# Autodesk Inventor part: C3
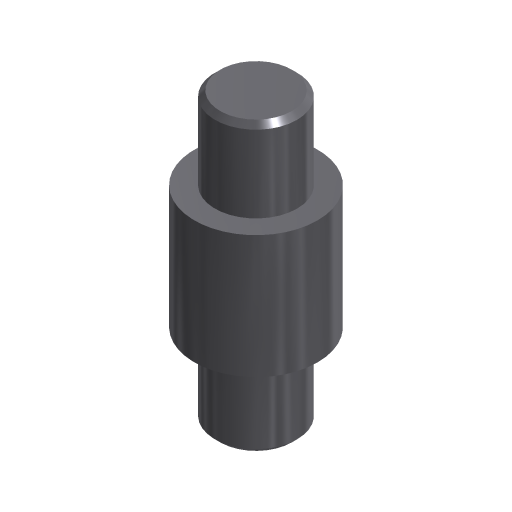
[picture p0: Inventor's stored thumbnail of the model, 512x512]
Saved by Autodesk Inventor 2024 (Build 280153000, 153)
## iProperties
Company: ATC
Shininess: 20.0
Angle Display Precision: 2
Document Length Units: 11269
Document Angle Units: 11279
Document Time Units: 11290
Document Mass Units: 11283
Document Length Units Precision: 3
Document Angle Units Precision: 2
Created: 2023-03
Part Number: C3
Material: Kurs-AJ
Document SubType Name: Modelowanie
Designer: Andrzej Jaskulski
Density: 1 g/cm^3
Appearance: Metal-stal (polerowana)
Checked By: A.J.
Engr Approved By: Andrzej Jaskulski
Mfg Approved By: Andrzej Jaskulski
Authority: A.J.
Density: 0.0
Volumn: 0.0
Area: 0.0
PropertySet Name: Model Information
Control State: 0
Master: False
Checked Out: False
Title: A.J.: Kurs R2024-MEP
Author: Andrzej Jaskulski
Revision Number: 1/24
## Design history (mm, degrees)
node "Początek"
  node "Płaszczyzna YZ"
  node "Płaszczyzna XZ"
  node "Płaszczyzna XY"
  node "Oś X"
  node "Oś Y"
  node "Oś Z"
sketch "Szkic1"
  geometry: C1 r 4 at (41.919, -38.642) reference; C2 r 6 at (41.919, -38.642)
  constraints: 1 centre point, 1 coincident
  dimensions: "d0" = 2 radial gap between concentric circles of C2 C1
extrude "Wyciągnięcie proste1" new body sketch "Szkic1" distance "d1" = 12; taper "d2" = 0 deg
extrude "Wyciągnięcie proste2" join sketch "Szkic1" distance "d3" = 8; taper "d4" = 0 deg
node "Płaszczyzna konstrukcyjna1"
chamfer "Faza1" distance "d6" = 0.5; stored, may be unused: second distance "d7" = 0.5, angle "d9" = 45 deg
mirror "Lustro1"
node "Bryła1"
node "Korpusy bryłowe"
node "Korpusy powierzchniowe"
node "Punkt środkowy"
other parameters: "d5" = -6 (= -0.5 x d1), "d8" = 0
